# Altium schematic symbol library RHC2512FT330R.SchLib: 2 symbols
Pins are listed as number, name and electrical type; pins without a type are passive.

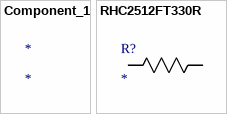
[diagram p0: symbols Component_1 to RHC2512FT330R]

## Component_1
designator *

## RHC2512FT330R
designator R?
No Description Available; Mfr_Name: Stackpole International
footprint STA_RHC2512_STP
pins: 1, 2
